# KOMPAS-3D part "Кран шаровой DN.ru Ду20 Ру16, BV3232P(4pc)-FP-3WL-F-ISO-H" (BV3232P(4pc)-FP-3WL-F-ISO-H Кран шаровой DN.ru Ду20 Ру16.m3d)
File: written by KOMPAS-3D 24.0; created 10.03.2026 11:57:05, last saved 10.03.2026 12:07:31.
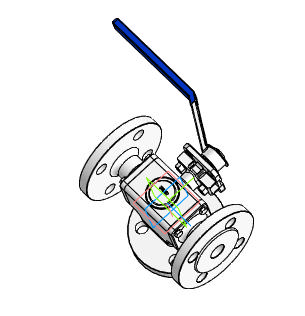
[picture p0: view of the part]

Document properties: Автор: R2D2; Полное имя файла: BV3232P(4pc)-FP-3WL-F-ISO-H Кран шаровой DN.ru Ду20 Ру16.cdw

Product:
- Part/product: Кран шаровой DN.ru Ду20 Ру16  | designation BV3232P(4pc)-FP-3WL-F-ISO-H
    Масса: 4.5
    Раздел спецификации: Прочие изделия
    Форматы листов документа: A2
    Примечание: D160-36356

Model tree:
1. Операция без истории:3

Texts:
  BV3232P(4pc)-FP-3WL-F-ISO-H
